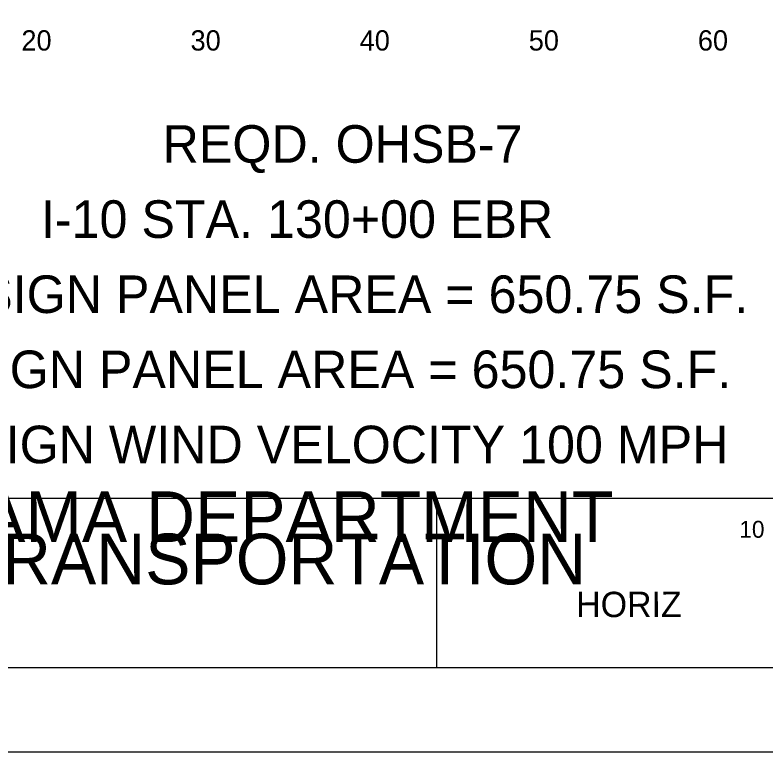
# Model space of a CAD drawing. Extents: x 2193008 to 2198143, y 1236112 to 1237864.
# Drawn here: x 2195753.23 to 2195797.63, y 1237118.04 to 1237161.61 of the extents above; entities that cross this region are included whole.
import ezdxf

# ---------------------------------------------------------------- set-up
doc = ezdxf.new("R2010")
doc.units = 0
for name, color, linetype in [('ANNO-SYMB', 7, 'Continuous'), ('ANNO-TXT', 7, 'Continuous'), ('Level 55', 7, 'Continuous'), ('LIMT-CSLINE', 7, 'Continuous'), ('M-ROADS', 7, 'Continuous'), ('SHT-BNDRY', 7, 'Continuous')]:
    doc.layers.add(name, color=color, linetype=linetype)

msp = doc.modelspace()

# ---------------------------------------------------------------- linework, layer by layer
msp.add_lwpolyline([(2195574.707, 1237133.046), (2195874.707, 1237133.046), (2195874.707, 1237323.046), (2195574.707, 1237323.046)], close=True)
at = {"layer": 'M-ROADS'}
msp.add_lwpolyline([(2195549.71, 1237118.036), (2195889.71, 1237118.036), (2195889.71, 1237338.036), (2195549.71, 1237338.036)], close=True, dxfattribs=at)
at = {"layer": 'SHT-BNDRY'}
msp.add_line((2195778.179, 1237123.036), (2195778.179, 1237133.046), dxfattribs=at)
msp.add_lwpolyline([(2195562.21, 1237123.036), (2195884.71, 1237123.036), (2195884.71, 1237333.036), (2195562.21, 1237333.036)], close=True, dxfattribs=at)

# ---------------------------------------------------------------- texts
at = {"layer": 'ANNO-SYMB'}
for s, height, p in [(' 10', 0.9991, (2195795.689, 1237130.7)), ('HORIZ', 1.4994, (2195786.412, 1237126.008))]:
    msp.add_text(s, height=height, rotation=0.0572, dxfattribs=at).set_placement(p)
at = {"layer": 'ANNO-TXT'}
for s, p in [('ALABAMA DEPARTMENT', (2195740.908, 1237130.446)), ('OF TRANSPORTATION', (2195743.319, 1237127.946))]:
    msp.add_text(s, height=3, rotation=360, dxfattribs=at).set_placement(p)
at = {"layer": 'Level 55'}
for s, p in [('REQD. OHSB-7', (2195761.953, 1237152.873)), ('I-10 STA. 130+00 EBR', (2195754.759, 1237148.431)), ('DESIGN SIGN PANEL AREA = 650.75 S.F.', (2195738.897, 1237143.989)), ('REQD. SIGN PANEL AREA = 650.75 S.F.', (2195739.873, 1237139.547)), ('DESIGN WIND VELOCITY 100 MPH', (2195746.567, 1237135.106))]:
    msp.add_text(s, height=2.22092, dxfattribs=at).set_placement(p)
at = {"layer": 'LIMT-CSLINE'}
for s, p in [('20', (2195753.606, 1237159.506)), ('30', (2195763.606, 1237159.506)), ('40', (2195773.606, 1237159.506)), ('50', (2195783.606, 1237159.506)), ('60', (2195793.606, 1237159.506))]:
    msp.add_text(s, height=1.2, dxfattribs=at).set_placement(p)

doc.saveas('drawing.dxf')
